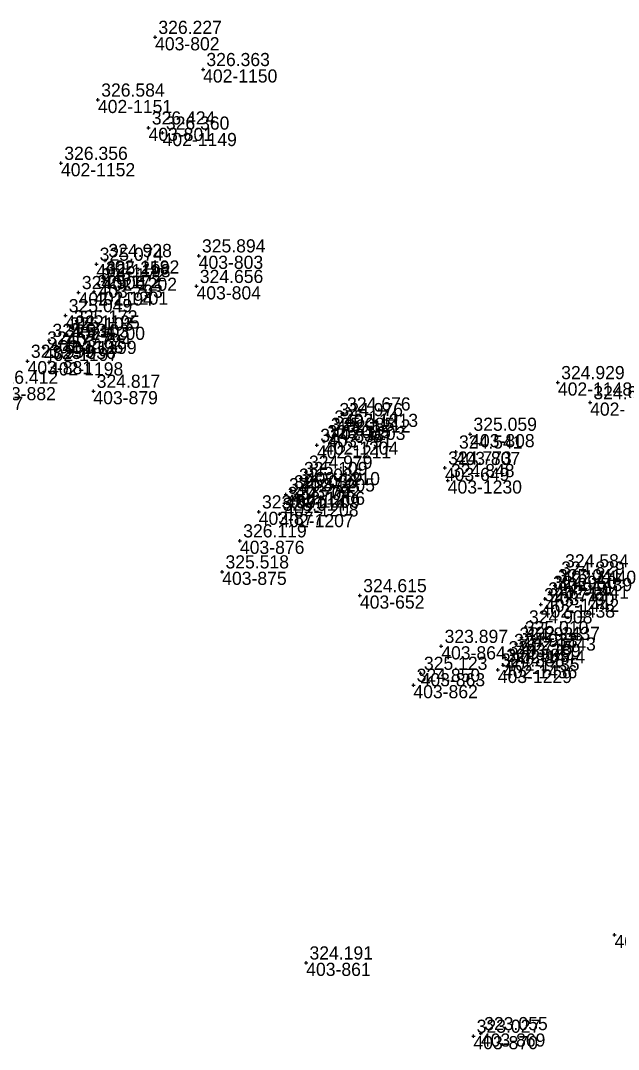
# Model space of a CAD drawing. Extents: x -829398 to -819400, y -1074439 to -1067977.
# Drawn here: x -824893.7 to -824839.1, y -1069684.9 to -1069591 of the extents above; entities that cross this region are included whole.
import ezdxf

# ---------------------------------------------------------------- set-up
doc = ezdxf.new("R2010")
doc.units = 0
for name, color, linetype in [('Vrstva 60', 7, 'Continuous'), ('Vrstva 61', 7, 'Continuous'), ('Čísla bodů_doměření_2012', 7, 'Continuous')]:
    doc.layers.add(name, color=color, linetype=linetype)

# ---------------------------------------------------------------- blocks, each defined once
blk = doc.blocks.new('BOD')
at = {"layer": 'Čísla bodů_doměření_2012'}
for p, q in [((-0.15, 0), (0.15, 0)), ((0, -0.15), (0, 0.15))]:
    blk.add_line(p, q, dxfattribs=at)

msp = doc.modelspace()

# ---------------------------------------------------------------- block references
at = {"layer": 'Vrstva 60'}
for p in [(-824881.402, -1069592.498), (-824877.012, -1069595.435), (-824886.623, -1069598.221), (-824881.999, -1069600.764), (-824880.715, -1069601.237), (-824889.999, -1069603.993), (-824877.416, -1069612.443), (-824886.766, -1069613.204), (-824885.969, -1069612.869), (-824886.181, -1069614.446), (-824886.581, -1069615.08), (-824877.615, -1069615.231), (-824888.389, -1069615.788), (-824886.981, -1069615.713), (-824889.588, -1069617.897), (-824889.105, -1069618.923), (-824891.079, -1069620.153), (-824889.87, -1069620.211), (-824889.488, -1069619.567), (-824891.558, -1069620.847), (-824893.049, -1069622.059), (-824891.092, -1069622.17), (-824887.037, -1069624.8), (-824844.595, -1069624.009), (-824841.654, -1069625.843), (-824864.854, -1069627.385), (-824864.156, -1069626.869), (-824865.311, -1069628.056), (-824865.961, -1069629.401), (-824865.636, -1069628.728), (-824852.612, -1069628.723), (-824866.612, -1069629.741), (-824853.934, -1069630.343), (-824867.64, -1069632.182), (-824854.921, -1069631.8), (-824868.55, -1069633.368), (-824868.096, -1069632.764), (-824854.662, -1069632.951), (-824869.467, -1069634.244), (-824869.004, -1069633.972), (-824869.589, -1069635.037), (-824871.931, -1069635.807), (-824870.039, -1069636.023), (-824873.648, -1069638.453), (-824875.267, -1069641.286), (-824844.233, -1069641.19), (-824844.888, -1069642.548), (-824844.595, -1069641.851), (-824862.683, -1069643.453), (-824845.332, -1069643.15), (-824846.155, -1069644.277), (-824845.776, -1069643.751), (-824847.541, -1069646.307), (-824847.914, -1069647.283), (-824855.251, -1069648.086), (-824848.407, -1069647.868), (-824849.405, -1069649.119), (-824848.9, -1069648.453), (-824850.092, -1069650.242), (-824849.608, -1069649.81), (-824857.137, -1069650.541), (-824857.8, -1069651.633), (-824839.415, -1069674.426), (-824867.592, -1069676.977), (-824852.316, -1069683.667), (-824851.63, -1069683.426)]:
    msp.add_blockref('BOD', p, dxfattribs=at)

# ---------------------------------------------------------------- texts
for s, p in [('403-802', (-824881.402, -1069593.698)), ('402-1150', (-824877.012, -1069596.635)), ('402-1151', (-824886.623, -1069599.421)), ('403-801', (-824881.999, -1069601.964)), ('402-1149', (-824880.715, -1069602.437)), ('402-1152', (-824889.999, -1069605.193)), ('403-803', (-824877.416, -1069613.643)), ('402-1193', (-824886.766, -1069614.404)), ('402-1192', (-824885.969, -1069614.069)), ('402-1202', (-824886.181, -1069615.646)), ('403-793', (-824886.581, -1069616.28)), ('403-804', (-824877.615, -1069616.431)), ('402-1194', (-824888.389, -1069616.988)), ('402-1201', (-824886.981, -1069616.913)), ('402-1195', (-824889.588, -1069619.097)), ('402-1200', (-824889.105, -1069620.123)), ('403-794', (-824889.488, -1069620.767)), ('402-1197', (-824891.558, -1069622.047)), ('402-1196', (-824891.079, -1069621.353)), ('402-1199', (-824889.87, -1069621.411)), ('403-881', (-824893.049, -1069623.259)), ('402-1198', (-824891.092, -1069623.37)), ('403-882', (-824896.356, -1069625.633)), ('403-879', (-824887.037, -1069626)), ('402-1148', (-824844.595, -1069625.209)), ('402-1147', (-824841.654, -1069627.043)), ('402-1212', (-824864.854, -1069628.585)), ('402-1213', (-824864.156, -1069628.069)), ('402-1203', (-824865.311, -1069629.256)), ('402-1204', (-824865.961, -1069630.601)), ('403-791', (-824865.636, -1069629.928)), ('403-808', (-824852.612, -1069629.923)), ('402-1211', (-824866.612, -1069630.941)), ('403-807', (-824853.934, -1069631.543)), ('402-1210', (-824867.64, -1069633.382)), ('403-649', (-824854.921, -1069633)), ('402-1205', (-824868.096, -1069633.964)), ('403-1230', (-824854.662, -1069634.151)), ('402-1206', (-824869.004, -1069635.172)), ('403-792', (-824868.55, -1069634.568)), ('402-1208', (-824869.589, -1069636.237)), ('402-1209', (-824869.467, -1069635.444)), ('403-877', (-824871.931, -1069637.007)), ('402-1207', (-824870.039, -1069637.223)), ('403-876', (-824873.648, -1069639.653)), ('403-875', (-824875.267, -1069642.486)), ('402-1440', (-824844.233, -1069642.39)), ('402-1441', (-824844.888, -1069643.748)), ('402-1439', (-824844.595, -1069643.051)), ('403-652', (-824862.683, -1069644.653)), ('403-790', (-824845.332, -1069644.35)), ('402-1438', (-824846.155, -1069645.477)), ('402-1442', (-824845.776, -1069644.951)), ('402-1437', (-824847.541, -1069647.507)), ('402-1443', (-824847.914, -1069648.483)), ('403-864', (-824855.251, -1069649.286)), ('403-789', (-824848.407, -1069649.068)), ('402-1435', (-824849.405, -1069650.319)), ('402-1444', (-824848.9, -1069649.653)), ('402-1436', (-824849.608, -1069651.01)), ('403-863', (-824857.137, -1069651.741)), ('403-1229', (-824850.092, -1069651.442)), ('403-862', (-824857.8, -1069652.833)), ('402-1527', (-824839.415, -1069675.626)), ('403-861', (-824867.592, -1069678.177)), ('403-870', (-824852.316, -1069684.867)), ('403-869', (-824851.63, -1069684.626))]:
    msp.add_text(s, height=1.2, dxfattribs=at).set_placement(p)
at = {"layer": 'Vrstva 61'}
for s, p in [('326.227', (-824881.102, -1069592.198)), ('326.363', (-824876.712, -1069595.135)), ('326.584', (-824886.323, -1069597.921)), ('326.424', (-824881.699, -1069600.464)), ('326.360', (-824880.415, -1069600.937)), ('326.356', (-824889.699, -1069603.693)), ('324.928', (-824885.669, -1069612.569)), ('325.894', (-824877.116, -1069612.143)), ('325.074', (-824886.466, -1069612.904)), ('325.258', (-824885.881, -1069614.146)), ('324.906', (-824888.089, -1069615.488)), ('325.172', (-824886.681, -1069615.413)), ('325.172', (-824886.281, -1069614.78)), ('324.656', (-824877.315, -1069614.931)), ('325.049', (-824889.288, -1069617.597)), ('325.103', (-824889.188, -1069619.267)), ('325.172', (-824888.805, -1069618.623)), ('324.934', (-824890.779, -1069619.853)), ('325.103', (-824889.57, -1069619.911)), ('324.777', (-824891.258, -1069620.547)), ('323.999', (-824892.749, -1069621.759)), ('325.036', (-824890.792, -1069621.87)), ('324.929', (-824844.295, -1069623.709)), ('326.412', (-824896.056, -1069624.133)), ('324.817', (-824886.737, -1069624.5)), ('324.696', (-824841.354, -1069625.543)), ('326.437', (-824899.258, -1069626.513)), ('324.676', (-824863.856, -1069626.569)), ('325.174', (-824865.011, -1069627.756)), ('324.976', (-824864.554, -1069627.085)), ('325.085', (-824865.336, -1069628.428)), ('325.059', (-824852.312, -1069628.423)), ('324.836', (-824866.312, -1069629.441)), ('325.085', (-824865.661, -1069629.101)), ('324.541', (-824853.634, -1069630.043)), ('324.773', (-824854.621, -1069631.5)), ('325.109', (-824867.796, -1069632.464)), ('324.979', (-824867.34, -1069631.882)), ('325.036', (-824868.25, -1069633.068)), ('324.848', (-824854.362, -1069632.651)), ('324.874', (-824869.167, -1069633.944)), ('325.036', (-824868.704, -1069633.672)), ('324.704', (-824869.289, -1069634.737)), ('323.891', (-824871.631, -1069635.507)), ('325.014', (-824869.739, -1069635.723)), ('326.119', (-824873.348, -1069638.153)), ('325.518', (-824874.967, -1069640.986)), ('324.584', (-824843.933, -1069640.89)), ('324.829', (-824844.295, -1069641.551)), ('324.950', (-824845.032, -1069642.85)), ('325.041', (-824844.588, -1069642.248)), ('324.615', (-824862.383, -1069643.153)), ('324.950', (-824845.476, -1069643.451)), ('324.712', (-824845.855, -1069643.977)), ('324.908', (-824847.241, -1069646.007)), ('324.933', (-824848.107, -1069647.568)), ('325.010', (-824847.614, -1069646.983)), ('323.897', (-824854.951, -1069647.786)), ('324.933', (-824848.6, -1069648.153)), ('324.715', (-824849.105, -1069648.819)), ('325.123', (-824856.837, -1069650.241)), ('324.888', (-824849.792, -1069649.942)), ('324.585', (-824849.308, -1069649.51)), ('324.850', (-824857.5, -1069651.333)), ('324.191', (-824867.292, -1069676.677)), ('323.055', (-824851.33, -1069683.126)), ('323.027', (-824852.016, -1069683.367))]:
    msp.add_text(s, height=1.2, dxfattribs=at).set_placement(p)

doc.saveas('drawing.dxf')
